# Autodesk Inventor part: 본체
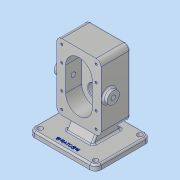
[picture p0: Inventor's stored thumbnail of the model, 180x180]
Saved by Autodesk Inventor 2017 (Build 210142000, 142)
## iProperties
Part Number: 본체
Material: 알루미늄 6061
Document SubType Name: Modeling
Designer: MRC
Density: 2.7 g/cm^3
Appearance: 알루미늄 - 평지
Mass: 1472.54 g
Surface Area: 818.394 cm^2
Volume: 545.387 cm^3
Author: MRC
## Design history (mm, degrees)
sketch "스케치1"
  geometry: L1 (-40, -60)-(40, -60); L2 (40, -60)-(40, 60); L3 (40, 60)-(-40, 60); L4 (-40, 60)-(-40, -60); 3 further points
  constraints: 8 end point, 2 midpoint, 2 parallel, 1 horizontal, 1 horizontal alignment, 1 perpendicular, 1 vertical alignment
  dimensions: "d0" = 80 distance of L3.end L2.end; "d1" = 120 distance of L2.end L1.end
extrude "돌출1" new body sketch "스케치1" distance "d2" = 14; taper "d4" = 0 deg; dims "d3" = 39, "d5" = 0
fillet "모깎기1" dims "d6" = 9
sketch "스케치2"
  geometry: A1 r 9 centre (-31, -51) between (-40, -51) and (-31, -60) reference; A2 r 9 centre (31, -51) between (31, -60) and (40, -51) reference; A3 r 9 centre (31, 51) between (40, 51) and (31, 60) reference; A4 r 9 centre (-31, 51) between (-31, 60) and (-40, 51) reference; 9 further points
  constraints: 4 coincident
  dimensions: "d7" = 29 distance of point (31, 51) point (31, 22); "d8" = 44 distance of point (31, -22) point (31, 22); "d9" = 29 distance of point (-31, 51) point (-31, 22); "d10" = 44 distance of point (-31, -22) point (-31, 22); "d12" = 31 horizontal distance of point (0, 0) point (31, 22); "d13" = 31 horizontal distance of point (0, 0) point (-31, 22); "d14" = 31 horizontal distance of point (-31, -22) point (0, 0); "d15" = 31 horizontal distance of point (31, -22) point (0, 0)
hole "구멍1" sketch "스케치2" at (-31, 51), (31, 51), (31, -51), (-31, -51), (-31, 22), (31, 22), (-31, -22), (31, -22) diameter "d16" = 4.134; stored, may be unused: countersink angle "d20" = 90 deg, drill point angle "d22" = 118 deg; dims "d17" = 10, "d18" = 4, "d19" = 2, "d21" = 12
sketch "스케치3"
  geometry: L1 (0, -22)-(0, 22); L2 (24, -22)-(24, 22); L3 (-24, 22)-(-24, -22); A1 r 24 centre (0, -22) between (-24, -22) and (24, -22); A2 r 24 centre (0, 22) between (24, 22) and (-24, 22); 2 further points
  constraints: 8 end point, 4 point on circle, 4 tangent, 2 centre point, 1 coincident, 1 midpoint, 1 parallel, 1 vertical
  dimensions: "d23" = 48 diameter of A2; "d24" = 44 distance of L1.start L1.end
extrude "돌출2" cut sketch "스케치3" distance "d25" = 29; taper "d26" = 0 deg
sketch "스케치5"
  geometry: C1 r 11 at (-39, 51); 1 further point
  constraints: 1 centre point, 1 coincident
  dimensions: "d28" = 22 diameter of C1
extrude "돌출3" join sketch "스케치5" distance "d29" = 8; taper "d30" = 0 deg
sketch "스케치7"
  geometry: C1 r 11 at (0, 0) reference; 1 further point
  constraints: 1 coincident
hole "구멍3" sketch "스케치7" at (0, 0) diameter "d38" = 8.376; stored, may be unused: countersink angle "d42" = 90 deg, drill point angle "d44" = 118 deg; dims "d39" = 20, "d40" = 4, "d41" = 2, "d43" = 27.3
sketch "스케치11"
  geometry: A1 r 24 centre (0, 22) between (24, 22) and (-24, 22) reference; 2 further points
  constraints: 1 coincident
hole "구멍4" sketch "스케치11" at (0, 22) diameter "d48" = 17; stored, may be unused: countersink angle "d52" = 90 deg, drill point angle "d54" = 118 deg; dims "d49" = 20, "d50" = 25, "d51" = 15, "d53" = 27.3
sketch "스케치12"
  geometry: C1 r 8.5 at (0, 22) reference; C2 r 19 at (0, 22); 1 further point
  constraints: 1 centre point, 1 coincident
  dimensions: "d55" = 38 diameter of C2
extrude "돌출4" join sketch "스케치12" distance "d56" = 17; taper "d57" = 0 deg
sketch "스케치13"
  geometry: C1 r 8.5 at (0, 0) reference; C2 r 19 at (0, 0) reference; C3 r 14 at (0, 0); 1 further point
  constraints: 1 centre point, 1 coincident
  dimensions: "d58" = 28 diameter of C3
extrude "돌출5" cut sketch "스케치13" distance "d59" = 7.3; taper "d60" = 0 deg
fillet "모깎기2" dims "d61" = 0.5
chamfer "모따기1" distance "d62" = 0.7; stored, may be unused: second distance "d63" = 2, angle "d64" = 30 deg
sketch "스케치15"
  geometry: C1 r 12.5 at (0, -22); A1 r 24 centre (0, -22) between (-24, -22) and (24, -22) reference; 1 further point
  constraints: 1 centre point, 1 coincident
  dimensions: "d68" = 25 diameter of C1
extrude "돌출6" cut sketch "스케치15" distance "d69" = 15; taper "d70" = 0 deg
chamfer "모따기2" distance "d65" = 1; stored, may be unused: second distance "d66" = 2, angle "d67" = 30 deg
fillet "모깎기3" dims "d71" = 3
node "작업 평면1"
sketch "스케치16"
  geometry: L1 (60, 44)-(-60, 44); L2 (-60, 44)-(-60, -56); L3 (-60, -56)-(60, -56); L4 (60, -56)-(60, 44); L5 (-19, -56)-(19, -56) reference; 2 further points
  constraints: 8 end point, 2 midpoint, 2 parallel, 1 horizontal, 1 perpendicular, 1 vertical alignment
  dimensions: "d72" = 120 distance of L3.end L2.end; "d73" = 100 distance of L2.end L1.end
extrude "돌출7" join sketch "스케치16" distance "d74" = 10; taper "d75" = 0 deg
fillet "모깎기4" dims "d76" = 10
sketch "스케치17"
  geometry: A1 r 10 centre (50, -34) between (50, -44) and (60, -34) reference; A2 r 10 centre (50, 46) between (60, 46) and (50, 56) reference; A3 r 10 centre (-50, 46) between (-50, 56) and (-60, 46) reference; A4 r 10 centre (-50, -34) between (-60, -34) and (-50, -44) reference; 5 further points
  constraints: 4 coincident
hole "구멍5" sketch "스케치17" at (-50, -34), (-50, 46), (50, -34), (50, 46) diameter "d77" = 9; stored, may be unused: countersink angle "d81" = 90 deg, drill point angle "d83" = 118 deg; dims "d78" = 20, "d79" = 25, "d80" = 15, "d82" = 27.3
sketch "스케치21"
  geometry: L1 (-80, 14)-(-60, 2.453); L2 (-80, -39)-(-60, -27.453); L3 (-80, -46)-(-80, 34) reference; L4 (-60, -39)-(-60, 14) reference; L5 (-80, -56)-(-90, -56) reference; 1 further point
  constraints: 4 end point, 4 point on line
  dimensions: "d91" = 17 distance from line of L2.start L5; "d92" = 53 distance of L2.start L1.start; "d93" = 60 deg angle of L1 L3; "d94" = 60 deg angle of L3 L2
extrude "돌출8" join sketch "스케치21" stored distance "d95" = 48; taper "d96" = 0 deg
fillet "모깎기5" dims "d97" = 3
fillet "모깎기6" dims "d98" = 3
sketch "스케치22"
  geometry: L1 (-60, 46)-(-60, -34) reference; L2 (-50, -44)-(50, -44) reference; 2 further points
  constraints: 1 other
  dimensions: "d99" = 60 distance from line of L1 point (0, -34); "d100" = 10 distance from line of point (0, -34) L2
feature "엠보싱1" sketch "스케치22" dims "d0" = 80, "d1" = 120, "d101" = 0.5, "d102" = 0
node "솔리드1"
mirror "미러1"
